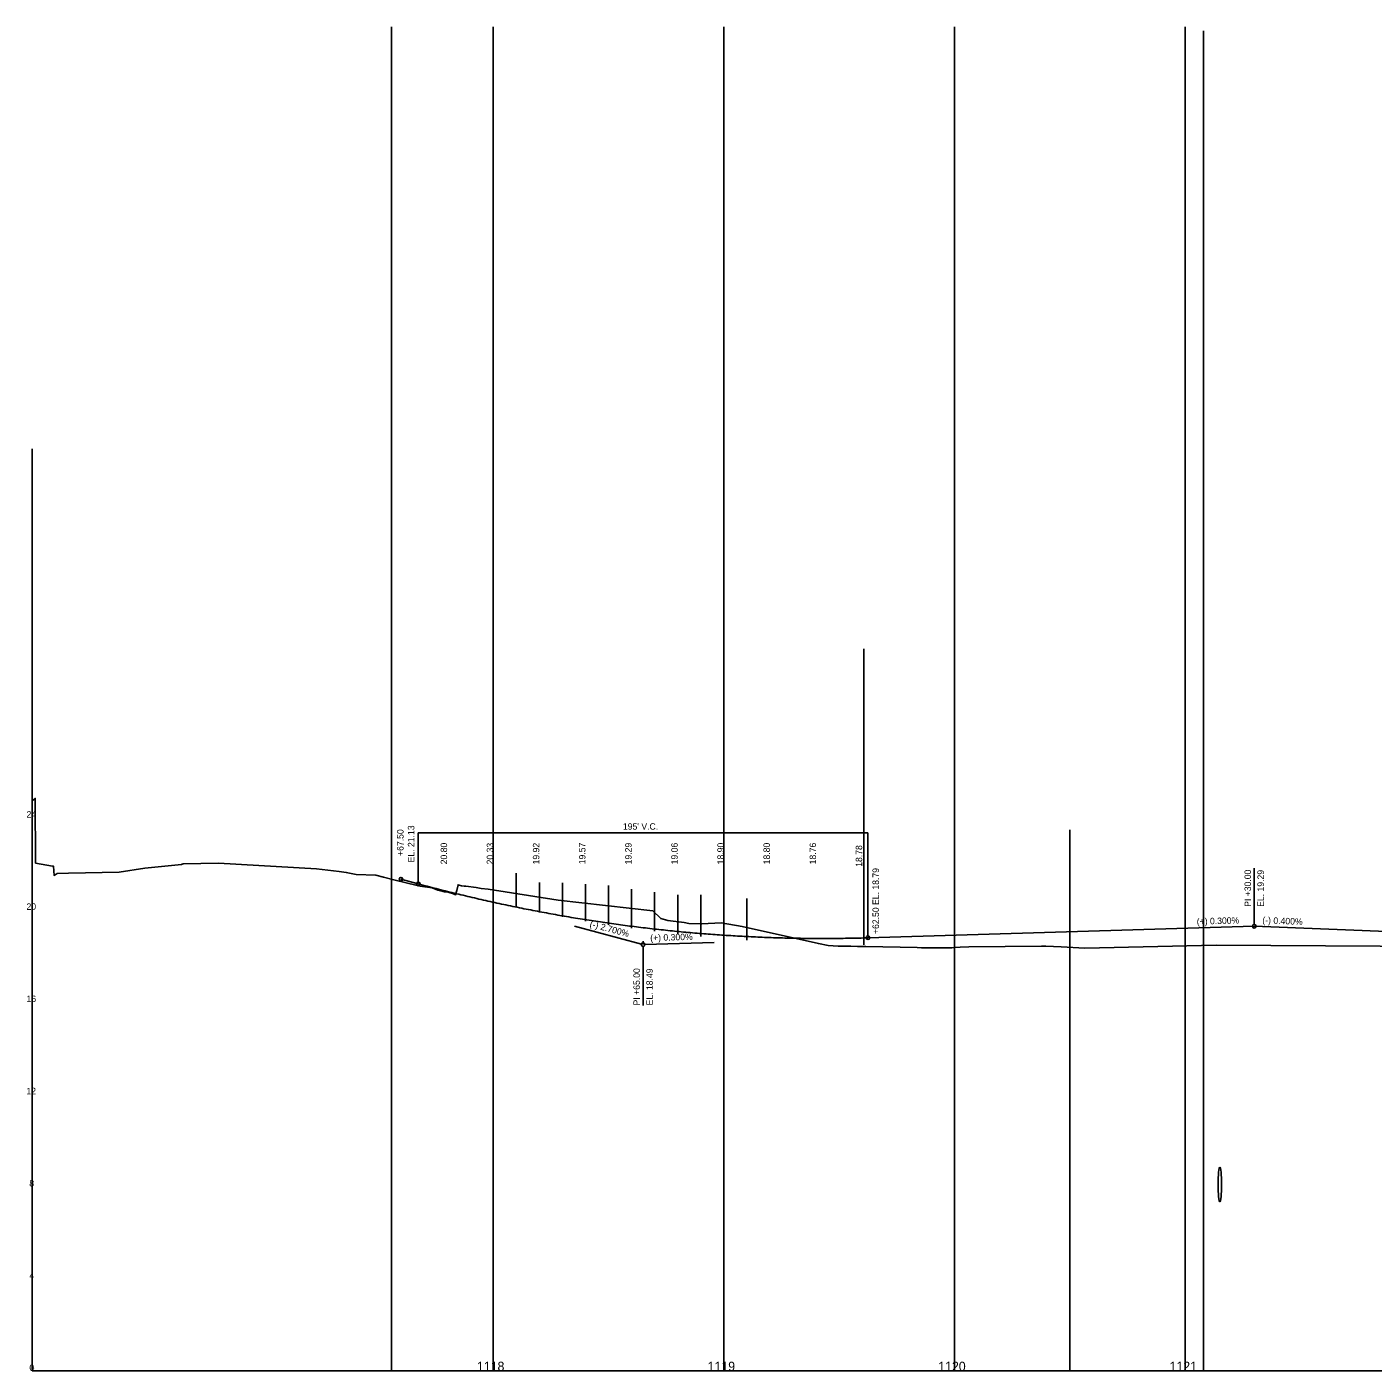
# Model space of a CAD drawing. Extents: x 1409 to 6106, y -2180 to -1584.
# Drawn here: x 1409 to 1992, y -2180 to -1597 of the extents above; entities that cross this region are included whole.
import ezdxf

# ---------------------------------------------------------------- set-up
doc = ezdxf.new("R2010")
doc.units = 0
for name, color, linetype in [('CLConst_dp', 7, 'Continuous'), ('LaneLine', 7, 'Continuous'), ('Miscellaneous0', 7, 'Continuous'), ('NonPlottingEle_dp', 7, 'Continuous'), ('Pedestal_ep', 7, 'Continuous'), ('PipeCulvert_ep', 7, 'Continuous'), ('StationTicS_dp', 7, 'Continuous'), ('TextLabel', 7, 'Continuous'), ('TextProfLabel', 7, 'Continuous'), ('TextPtLabel', 7, 'Continuous')]:
    doc.layers.add(name, color=color, linetype=linetype)

msp = doc.modelspace()

# ---------------------------------------------------------------- linework, layer by layer
at = {"layer": 'CLConst_dp'}
for q in [(1410.73, -1779.71), (6032.47, -2179.71), (1410.73, -2179.71)]:
    msp.add_line((1410.73, -2179.71), q, dxfattribs=at)
at = {"layer": 'Miscellaneous0'}
for p, q in [((1610.73, -2179.71), (1610.73, -1596.74)), ((1710.73, -2179.71), (1710.73, -1596.74)), ((1810.73, -2179.71), (1810.73, -1596.74)), ((1910.73, -2179.71), (1910.73, -1596.74))]:
    msp.add_line(p, q, dxfattribs=at)
at = {"layer": 'NonPlottingEle_dp'}
for p, q in [((1578.23, -1946.34), (1773.23, -1946.34)), ((1578.23, -1946.34), (1578.23, -1967.64)), ((1773.23, -1946.34), (1773.23, -1991.04)), ((1940.73, -1986.01), (1940.73, -1961.61)), ((1645.99, -1986.74), (1674.96, -1994.56)), ((1675.73, -1995.56), (1675.73, -2021.16)), ((1706.52, -1993.84), (1676.53, -1994.74))]:
    msp.add_line(p, q, dxfattribs=at)
for centre in [(1570.73, -1966.41), (1578.23, -1968.44), (1940.73, -1986.81), (1675.73, -1994.76), (1773.23, -1991.84)]:
    msp.add_circle(centre, 0.8, dxfattribs=at)
at = {"layer": 'Pedestal_ep'}
msp.add_line((1860.73, -2179.71), (1860.73, -1944.99), dxfattribs=at)
at = {"layer": 'PipeCulvert_ep'}
msp.add_ellipse((1925.83, -2098.81), major_axis=(0, 7.5), ratio=0.1, dxfattribs=at)
at = {"layer": 'StationTicS_dp'}
msp.add_lwpolyline([(1410.73, -1931.93), (1411.29, -1932.14), (1412.1, -1931.39), (1412.27, -1959.46), (1419.6, -1960.72), (1420.01, -1960.76), (1420.29, -1964.74), (1421.58, -1963.93), (1426.53, -1963.74), (1448.56, -1963.41), (1459.65, -1961.69), (1475.53, -1959.99), (1475.84, -1959.88), (1476.22, -1959.78), (1491.66, -1959.48), (1534.1, -1961.95), (1543.94, -1963.12), (1546.99, -1963.46), (1551.24, -1964.31), (1559.82, -1964.6), (1563.12, -1965.53), (1567.65, -1966.71), (1573.57, -1968.16), (1579.12, -1969.44), (1584.27, -1970.21), (1586.66, -1971.16), (1587.34, -1971.28), (1588.07, -1971.45), (1589.59, -1971.88), (1591.16, -1972.07), (1593.49, -1972.78), (1594.44, -1973.19), (1594.89, -1971.31), (1595.51, -1968.85), (1596.01, -1969.02), (1596.93, -1969.3), (1598.13, -1969.43), (1598.91, -1969.5), (1603.29, -1969.97), (1605.47, -1970.39), (1608.53, -1970.78), (1638.88, -1975.44), (1679.93, -1980.16), (1683.36, -1983.47), (1686.38, -1984.34), (1693.56, -1985.25), (1695.61, -1985.66), (1701.16, -1985.76), (1709.52, -1985.4), (1718.67, -1986.97), (1751.72, -1994.34), (1755.99, -1995.11), (1760.38, -1995.46), (1765.87, -1995.5), (1768.72, -1995.54), (1772.35, -1995.54), (1794.51, -1996.05), (1796.46, -1996.14), (1799.9, -1996.22), (1801.9, -1996.2), (1803.06, -1996.13), (1805.88, -1996.21), (1807.25, -1996.24), (1809.59, -1996.13), (1810.92, -1996.03), (1813.28, -1995.9), (1816.94, -1995.76), (1848.49, -1995.49), (1849.01, -1995.45), (1850.33, -1995.49), (1856.98, -1995.75), (1867.22, -1996.4), (1924.29, -1995.09), (2019.13, -1995.61)], dxfattribs=at)
msp.add_lwpolyline([(1410.73, -1931.93), (1411.29, -1932.14), (1412.1, -1931.39), (1412.27, -1959.46), (1419.6, -1960.72), (1420.01, -1960.76), (1420.29, -1964.74), (1421.58, -1963.93), (1426.53, -1963.74), (1448.56, -1963.41), (1459.65, -1961.69), (1475.53, -1959.99), (1475.84, -1959.88), (1476.22, -1959.78), (1491.66, -1959.48), (1534.1, -1961.95), (1543.94, -1963.12), (1546.99, -1963.46), (1551.24, -1964.31), (1559.82, -1964.6), (1563.12, -1965.53), (1567.65, -1966.71), (1573.57, -1968.16), (1579.12, -1969.44), (1584.27, -1970.21), (1586.66, -1971.16), (1587.34, -1971.28), (1588.07, -1971.45), (1589.59, -1971.88), (1591.16, -1972.07), (1593.49, -1972.78), (1594.44, -1973.19), (1594.89, -1971.31), (1595.51, -1968.85), (1596.01, -1969.02), (1596.93, -1969.3), (1598.13, -1969.43), (1598.91, -1969.5), (1603.29, -1969.97), (1605.47, -1970.39), (1608.53, -1970.78), (1638.88, -1975.44), (1679.93, -1980.16), (1683.36, -1983.47), (1686.38, -1984.34), (1693.56, -1985.25), (1695.61, -1985.66), (1701.16, -1985.76), (1709.52, -1985.4), (1718.67, -1986.97), (1751.72, -1994.34), (1755.99, -1995.11), (1760.38, -1995.46), (1765.87, -1995.5), (1768.72, -1995.54), (1772.35, -1995.54), (1794.51, -1996.05), (1796.46, -1996.14), (1799.9, -1996.22), (1801.9, -1996.2), (1803.06, -1996.13), (1805.88, -1996.21), (1807.25, -1996.24), (1809.59, -1996.13), (1810.92, -1996.03), (1813.28, -1995.9), (1816.94, -1995.76), (1848.49, -1995.49), (1849.01, -1995.45), (1850.33, -1995.49), (1856.98, -1995.75), (1867.22, -1996.4), (1924.29, -1995.09), (2019.13, -1995.61)], dxfattribs=at)
at = {"layer": 'TextLabel'}
for p, q in [((1566.59, -2179.71), (1566.59, -1596.74)), ((1918.73, -2179.71), (1918.73, -1598.37)), ((1771.44, -1994.82), (1771.44, -1866.49)), ((1610.73, -1976.51), (1610.73, -1963.53)), ((1620.73, -1978.71), (1620.73, -1963.75)), ((1630.73, -1980.81), (1630.73, -1967.82)), ((1640.73, -1982.81), (1640.73, -1968.05)), ((1650.73, -1984.61), (1650.73, -1968.62)), ((1660.73, -1986.21), (1660.73, -1969.21)), ((1670.73, -1987.71), (1670.73, -1970.71)), ((1680.73, -1989.01), (1680.73, -1972.01)), ((1690.73, -1990.21), (1690.73, -1973.21)), ((1700.73, -1991.31), (1700.73, -1973.21)), ((1710.73, -1992.11), (1710.73, -1974.01)), ((1720.73, -1992.91), (1720.73, -1974.81)), ((1675.73, -1994.76), (1675.73, -1993.33)), ((1810.73, -1993.91), (1810.73, -1992.2)), ((1410.73, -2039.71), (1410.73, -2039.71))]:
    msp.add_line(p, q, dxfattribs=at)
at = {"layer": 'TextPtLabel'}
for p, q in [((1570.73, -1966.41), (1578.23, -1968.44)), ((1773.23, -1991.84), (1940.73, -1986.81)), ((1940.73, -1986.81), (2200.73, -1997.21))]:
    msp.add_line(p, q, dxfattribs=at)
msp.add_spline([(1578.23, -1968.44), (1582.13, -1969.48), (1586.03, -1970.5), (1589.93, -1971.49), (1593.83, -1972.46), (1597.73, -1973.41), (1601.63, -1974.34), (1605.53, -1975.24), (1609.43, -1976.11), (1613.33, -1976.97), (1617.23, -1977.8), (1621.13, -1978.61), (1625.03, -1979.39), (1628.93, -1980.15), (1632.83, -1980.89), (1636.73, -1981.6), (1640.63, -1982.29), (1644.53, -1982.96), (1648.43, -1983.6), (1652.33, -1984.22), (1656.23, -1984.82), (1660.13, -1985.39), (1664.03, -1985.94), (1667.93, -1986.47), (1671.83, -1986.97), (1675.73, -1987.45), (1679.63, -1987.91), (1683.53, -1988.34), (1687.43, -1988.75), (1691.33, -1989.14), (1695.23, -1989.5), (1699.13, -1989.84), (1703.03, -1990.15), (1706.93, -1990.45), (1710.83, -1990.72), (1714.73, -1990.96), (1718.63, -1991.18), (1722.53, -1991.38), (1726.43, -1991.56), (1730.33, -1991.71), (1734.23, -1991.84), (1738.13, -1991.95), (1742.03, -1992.03), (1745.93, -1992.09), (1749.83, -1992.12), (1753.73, -1992.13), (1757.63, -1992.12), (1761.53, -1992.09), (1765.43, -1992.03), (1769.33, -1991.95), (1773.23, -1991.84)], degree=3, dxfattribs=at)

# ---------------------------------------------------------------- texts
at = {"layer": 'CLConst_dp'}
for s, height, p in [('40', 0.118, (1410.73, -2179.12)), ('4', 0.118, (1410.73, -2179.32)), ('01', 0.118, (1410.73, -2178.33)), ('PGL_REV', 0.118, (1410.73, -2178.53)), ('111600.000000', 0.1181, (1410.73, -2178.73)), ('0', 0.118, (1410.73, -2178.92)), ('NOGAP', 0.118, (1410.73, -2179.51))]:
    msp.add_text(s, height=height, dxfattribs=at).set_placement(p)
at = {"layer": 'LaneLine'}
for s, rotation, p in [('(-) 2.700%', 344.89042, (1652.37, -1987.01)), ('(+) 0.300%', 1.71836, (1915.86, -1986.16)), ('(-) 0.400%', 357.70939, (1944.21, -1985.55)), ('(+) 0.300%', 1.71836, (1678.85, -1993.27))]:
    msp.add_text(s, height=2.8, rotation=rotation, dxfattribs=at).set_placement(p)
at = {"layer": 'NonPlottingEle_dp'}
for s, p in [('EL. 21.13', (1576.51, -1959.13)), ('+67.50 ', (1571.84, -1956.32)), ('20.80', (1590.73, -1959.97)), ('20.33', (1610.73, -1960.01)), ('19.92', (1630.73, -1960.01)), ('19.57', (1650.73, -1959.94)), ('19.29', (1670.73, -1959.98)), ('19.06', (1690.73, -1959.98)), ('18.90', (1710.73, -1959.97)), ('18.80', (1730.73, -1959.97)), ('18.76', (1750.73, -1959.98)), ('18.78', (1770.73, -1961.04)), ('+62.50 EL. 18.79', (1778, -1990.19)), ('PI +30.00', (1939.33, -1978.41)), ('EL. 19.29', (1944.93, -1978.41)), ('PI +65.00', (1674.33, -2021.16)), ('EL. 18.49', (1679.93, -2021.16))]:
    msp.add_text(s, height=2.8, rotation=90, dxfattribs=at).set_placement(p)
msp.add_text("195' V.C.", height=2.8, dxfattribs=at).set_placement((1666.97, -1944.94))
at = {"layer": 'TextLabel'}
for s, p in [('24', (1408.35, -1939.71)), ('24', (1408.35, -1939.71)), ('20', (1408.33, -1979.71)), ('20', (1408.33, -1979.71)), ('16', (1408.33, -2019.71)), ('16', (1408.33, -2019.71)), ('12', (1408.3, -2059.71)), ('12', (1408.3, -2059.71)), ('8', (1409.56, -2099.71)), ('8', (1409.56, -2099.71)), ('4', (1409.61, -2139.71)), ('4', (1409.61, -2139.71)), ('0', (1409.59, -2179.71)), ('0', (1409.59, -2179.71))]:
    msp.add_text(s, height=2.8, dxfattribs=at).set_placement(p)
at = {"layer": 'TextProfLabel'}
for s, p in [('1118', (1603.68, -2179.71)), ('1119', (1703.71, -2179.71)), ('1120', (1803.71, -2179.71)), ('1121', (1904.02, -2179.71))]:
    msp.add_text(s, height=4, dxfattribs=at).set_placement(p)

doc.saveas('drawing.dxf')
